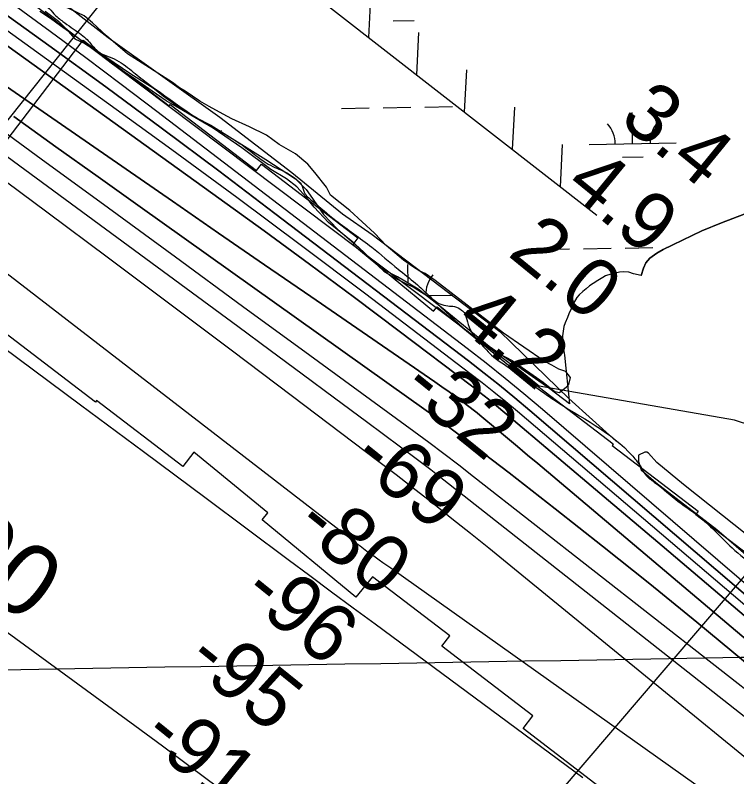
# Model space of a CAD drawing. Extents: x 3887375 to 3925618, y 296674 to 322633.
# Drawn here: x 3893263 to 3894095, y 314133 to 315011 of the extents above; entities that cross this region are included whole.
import ezdxf

# ---------------------------------------------------------------- set-up
doc = ezdxf.new("R2010")
doc.units = 0
for name, color, linetype in [('V-GRID-MAJR', 7, 'Continuous'), ('V-RIVR-EDGE', 7, 'Continuous'), ('V-RIVR-JETY', 7, 'Continuous'), ('V-RIVR-RANG', 7, 'Continuous'), ('V-RRAP-FSHR', 7, 'Continuous'), ('V-RRAP-RVMT', 7, 'Continuous'), ('V-TOPO-DPTH', 7, 'Continuous'), ('V-TOPO-MAJR', 7, 'Continuous'), ('V-TOPO-MINR', 7, 'Continuous'), ('V-TOPO-MINR-IDEN', 7, 'Continuous'), ('V-TOPO-SHOR', 7, 'Continuous'), ('V-TOPO-WATR', 7, 'Continuous'), ('V-WETL-SWMP', 7, 'Continuous')]:
    doc.layers.add(name, color=color, linetype=linetype)

msp = doc.modelspace()

# ---------------------------------------------------------------- linework, layer by layer
at = {"layer": 'V-GRID-MAJR'}
msp.add_spline([(3891444.7, 314225.88), (3896753.86, 314315.07), (3902063.01, 314405.04), (3907372.14, 314495.79), (3912681.27, 314587.3), (3917990.38, 314679.59), (3923299.47, 314772.65)], degree=3, dxfattribs=at)
at = {"layer": 'V-RIVR-EDGE'}
msp.add_spline([(3891928.45, 315977.82), (3891957.1, 315960.21), (3891975.01, 315952.59), (3891990.13, 315943.39), (3892009.63, 315930.59), (3892033.91, 315917.77), (3892077.69, 315895.35), (3892112.31, 315874.14), (3892145.74, 315852.54), (3892173.98, 315832.54), (3892316.06, 315752.48), (3892341.13, 315737.67), (3892375.37, 315721.25), (3892402.44, 315708.83), (3892426.71, 315696.01), (3892453.78, 315682.4), (3892471.29, 315671.99), (3892523.02, 315638.79), (3892560.03, 315617.57), (3892582.31, 315601.18), (3892604.59, 315586.77), (3892621.3, 315577.17), (3892636.02, 315565.57), (3892664.25, 315537.61), (3892674.17, 315522.84), (3892678.13, 315511.67), (3892682.1, 315505.28), (3892690.46, 315500.88), (3892696.83, 315498.47), (3892706.77, 315489.28), (3892723.47, 315474.49), (3892741.76, 315455.72), (3892761.64, 315438.13), (3892777.55, 315422.55), (3892805.39, 315399.37), (3892826.47, 315384.57), (3892845.56, 315369.38), (3892875, 315344.99), (3892902.83, 315321.41), (3892934.64, 315289.85), (3892954.52, 315270.67), (3892974.01, 315257.47), (3892987.54, 315247.07), (3892996.68, 315235.89), (3893002.63, 315225.52), (3893020.54, 315215.51), (3893037.65, 315206.7), (3893043.62, 315202.3), (3893054.76, 315193.5), (3893076.25, 315182.69), (3893088.99, 315175.48), (3893097.73, 315167.09), (3893110.86, 315156.7), (3893119.61, 315149.5), (3893128.77, 315145.5), (3893137.53, 315143.48), (3893147.48, 315138.28), (3893164.98, 315124.68), (3893182.88, 315109.1), (3893203.96, 315093.9), (3893217.49, 315085.9), (3893226.64, 315076.71), (3893239.37, 315067.91), (3893248.51, 315057.52), (3893271.97, 315035.94), (3893289.87, 315023.54), (3893300.23, 315019.93), (3893307.78, 315012.34), (3893318.12, 315003.55), (3893337.21, 314989.95), (3893344.77, 314983.95), (3893355.11, 314972.37), (3893362.66, 314966.37), (3893374.61, 314961.56), (3893394.9, 314948.76), (3893412.4, 314934.77), (3893439.06, 314915.57), (3893461.33, 314899.57), (3893504.71, 314873.56), (3893525, 314860.76), (3893540.52, 314849.16), (3893560.01, 314836.36), (3893578.33, 314827.95), (3893587.08, 314821.55), (3893592.64, 314815.96), (3893596.21, 314806.78), (3893605.35, 314796.8), (3893632.79, 314774.01), (3893674.16, 314743.22), (3893704.39, 314718.04), (3893724.67, 314701.65), (3893740.18, 314687.26), (3893752.51, 314678.07), (3893761.67, 314675.65), (3893769.64, 314674.84), (3893777.6, 314670.83), (3893781.18, 314666.84), (3893784.35, 314657.26), (3893789.1, 314645.69), (3893797.04, 314635.31), (3893812.15, 314618.94), (3893836.42, 314601.74), (3893870.23, 314576.95), (3893883.36, 314567.75), (3893974.86, 314502.16), (3893984.39, 314489.38), (3893990.75, 314479.8), (3894001.09, 314471.41), (3894027.34, 314450.22), (3894050.41, 314433.43), (3894069.1, 314416.64), (3894089.38, 314396.66), (3894117.62, 314375.07), (3894129.56, 314367.47), (3894149.44, 314351.08), (3894187.62, 314319.5), (3894217.45, 314293.92), (3894236.15, 314278.73), (3894249.67, 314267.94), (3894262.79, 314253.96), (3894279.09, 314238.38)], degree=3, dxfattribs=at)
at = {"layer": 'V-RIVR-JETY'}
for points in [[(3893297.79, 315015.6), (3893313.01, 315003.96), (3893321.96, 314995), (3893331.81, 314983.36), (3893343.45, 314977.99), (3893367.63, 314962.77), (3893396.28, 314943.07), (3893422.25, 314926.95), (3893433.89, 314918), (3893450.9, 314905.46), (3893471.5, 314892.93), (3893488.51, 314883.97), (3893552.08, 314844.57), (3893586.11, 314822.19), (3893598.64, 314809.65), (3893603.12, 314803.39), (3893618.34, 314781), (3893634.46, 314763.99), (3893658.64, 314743.39), (3893673.86, 314729.07), (3893688.18, 314715.64), (3893702.51, 314706.68), (3893713.26, 314701.31), (3893723.11, 314696.83), (3893742.8, 314684.3), (3893758.92, 314669.07), (3893779.52, 314650.27), (3893798.32, 314635.05), (3893818.91, 314621.62), (3893835.93, 314612.66), (3893871.74, 314587.59), (3893885.18, 314576.85), (3893890.55, 314575.95), (3893898.61, 314582.22), (3893901.29, 314584.91), (3893903.08, 314592.96), (3893897.71, 314600.13), (3893889.65, 314602.81), (3893881.59, 314607.29), (3893872.64, 314611.77), (3893826.08, 314644), (3893747.28, 314704.89), (3893735.64, 314712.95), (3893729.37, 314715.64), (3893722.21, 314720.11), (3893710.57, 314728.17), (3893690.87, 314745.18), (3893677.44, 314759.51), (3893648.79, 314785.48), (3893626.4, 314803.39), (3893621.92, 314812.34), (3893608.49, 314829.35), (3893600.43, 314839.2), (3893586.11, 314850.84), (3893567.3, 314861.59), (3893552.98, 314872.33), (3893533.28, 314882.18), (3893512.68, 314891.14), (3893502.83, 314896.51), (3893486.72, 314905.46), (3893475.97, 314911.73), (3893458.96, 314923.37), (3893452.69, 314926.95), (3893444.63, 314933.22), (3893392.7, 314966.35), (3893368.52, 314986.95), (3893352.41, 315002.17), (3893342.56, 315010.23), (3893312.11, 315024.55)], [(3894136.46, 314387.99), (3894033.49, 314469.73), (3894002.71, 314495.2), (3893993.15, 314505.82), (3893991.03, 314506.88), (3893988.91, 314506.88), (3893981.48, 314503.69), (3893981.48, 314496.26), (3893984.66, 314486.71), (3894001.64, 314471.85), (3894071.7, 314417.71), (3894116.29, 314379.5)]]:
    msp.add_lwpolyline(points, dxfattribs=at)
at = {"layer": 'V-RIVR-RANG'}
for p, q in [((3893474.49, 315166.64), (3892839.24, 314368.61)), ((3894256.41, 314543.27), (3893593.48, 313768.08))]:
    msp.add_line(p, q, dxfattribs=at)
at = {"layer": 'V-RRAP-FSHR'}
for p, q in [((3893670.74, 314985.25), (3893673.25, 315034.01)), ((3893725.93, 314942.2), (3893728.45, 314990.96)), ((3893781.13, 314899.15), (3893783.65, 314947.91)), ((3893836.33, 314856.1), (3893838.84, 314904.86)), ((3893891.52, 314813.05), (3893894.04, 314861.81))]:
    msp.add_line(p, q, dxfattribs=at)
for points in [[(3893118.1, 315414.89), (3893508.75, 315111.58), (3893933.55, 314780.27)], [(3892945.61, 315305.74), (3893066.47, 315208.61), (3893128.78, 315157.3), (3893179.77, 315133.47), (3893370.49, 314985.02), (3893498.9, 314893.39), (3893581.99, 314829.25), (3893640.53, 314781.6), (3893674.52, 314757.77), (3893821.81, 314645.98), (3893901.13, 314569.01), (3893955.89, 314519.53)], [(3893387.89, 315205.42), (3893508.75, 315111.58), (3893933.55, 314780.27)]]:
    msp.add_lwpolyline(points, dxfattribs=at)
at = {"layer": 'V-RRAP-RVMT'}
for p, q in [((3893238.49, 314847.17), (3893341.39, 314981.83)), ((3893341.39, 314981.83), (3893440.65, 314906.15)), ((3893440.65, 314906.15), (3893441.91, 314907.76)), ((3893441.91, 314907.76), (3893541.36, 314831.84)), ((3893541.36, 314831.84), (3893546.88, 314839.04)), ((3893546.88, 314839.04), (3893658.15, 314754.03)), ((3893658.15, 314754.03), (3893652.16, 314746.26)), ((3893652.16, 314746.26), (3893745.41, 314669.51)), ((3893745.41, 314669.51), (3893749.61, 314674.55)), ((3893749.61, 314674.55), (3893840.1, 314600.22)), ((3893355.69, 314564.59), (3893244.5, 314649.6)), ((3893840.1, 314600.22), (3893841.1, 314601.49)), ((3893841.1, 314601.49), (3893952.31, 314516.38)), ((3893357.03, 314566.38), (3893355.69, 314564.59)), ((3893456.4, 314490.41), (3893357.03, 314566.38)), ((3893952.31, 314516.38), (3893951.05, 314514.76)), ((3893951.05, 314514.76), (3894050.29, 314438.8)), ((3893468.93, 314506.94), (3893456.4, 314490.41)), ((3893554.25, 314436.9), (3893468.93, 314506.94)), ((3893547.7, 314428.93), (3893554.25, 314436.9)), ((3894050.29, 314438.8), (3894047.54, 314435.22)), ((3894047.54, 314435.22), (3894152.28, 314354.98)), ((3893655.81, 314339.96), (3893547.7, 314428.93)), ((3893674.99, 314363.29), (3893655.81, 314339.96)), ((3893764.18, 314295.24), (3893674.99, 314363.29)), ((3893754.98, 314283.22), (3893764.18, 314295.24)), ((3893859.8, 314202.83), (3893754.98, 314283.22)), ((3893848.65, 314188.24), (3893859.8, 314202.83)), ((3893947.76, 314112.32), (3893848.65, 314188.24))]:
    msp.add_line(p, q, dxfattribs=at)
at = {"layer": 'V-TOPO-DPTH'}
for points in [[(3894391.72, 314096.09), (3894339.08, 314141.49), (3894307.72, 314168.51), (3894276.34, 314195.5), (3894244.93, 314222.45), (3894213.5, 314249.37), (3893856.33, 314555.02), (3893838.93, 314569.66), (3893821.36, 314584.1), (3893803.55, 314598.24), (3893785.58, 314612.18), (3893562.45, 314782.26), (3893497.73, 314831.21), (3893432.77, 314879.85), (3893367.46, 314928.01), (3893301.91, 314975.85), (3893201.46, 315048.6)], [(3893201.46, 315048.6), (3893301.91, 314975.85), (3893367.46, 314928.01), (3893432.77, 314879.85), (3893497.73, 314831.21), (3893562.45, 314782.26), (3893785.58, 314612.18), (3893803.55, 314598.24), (3893821.36, 314584.1), (3893838.93, 314569.66), (3893856.33, 314555.02), (3894213.5, 314249.37), (3894244.93, 314222.45), (3894276.34, 314195.5), (3894307.72, 314168.51), (3894339.08, 314141.49), (3894391.72, 314096.09)], [(3895356.45, 313608.97), (3895202.61, 313769.6), (3895185.66, 313787.43), (3895168.79, 313805.34), (3895152.06, 313823.38), (3895135.42, 313841.49), (3895020.97, 313966.99), (3894983.49, 314007.86), (3894945.86, 314048.59), (3894907.99, 314089.11), (3894869.98, 314129.49), (3894830.99, 314168.81), (3894790.87, 314206.89), (3894621.93, 314337.77), (3894383.23, 314448.72), (3894091.96, 314544.03), (3893867.05, 314583.12), (3893838.43, 314605.12), (3893809.72, 314626.99), (3893780.94, 314648.78), (3893286.1, 315021.75), (3893269.81, 315033.97), (3893253.49, 315046.13)], [(3893207.69, 315008.59), (3893497.98, 314799.91), (3893550.27, 314762.02), (3893602.36, 314723.87), (3893654.15, 314685.31), (3893705.76, 314646.5), (3893788.97, 314583.4), (3893798.76, 314575.85), (3893808.46, 314568.21), (3893818.03, 314560.4), (3893827.53, 314552.5), (3893942.02, 314455.57), (3894008.66, 314399.08), (3894075.24, 314342.53), (3894141.75, 314285.88), (3894208.2, 314229.17), (3894366.18, 314094.17)], [(3893207.69, 315008.59), (3893497.98, 314799.91), (3893550.27, 314762.02), (3893602.36, 314723.87), (3893654.15, 314685.31), (3893705.76, 314646.5), (3893788.97, 314583.4), (3893798.76, 314575.85), (3893808.46, 314568.21), (3893818.03, 314560.4), (3893827.53, 314552.5), (3893942.02, 314455.57), (3894008.66, 314399.08), (3894075.24, 314342.53), (3894141.75, 314285.88), (3894208.2, 314229.17), (3894366.18, 314094.17)], [(3894340.52, 314092.09), (3893865.37, 314493.75), (3893853.76, 314503.55), (3893842.14, 314513.33), (3893830.51, 314523.09), (3893818.87, 314532.85), (3893798.58, 314549.81), (3893795.54, 314552.29), (3893793.99, 314553.5), (3893792.43, 314554.7), (3893779.45, 314564.51), (3893771.35, 314570.55), (3893763.2, 314576.51), (3893754.96, 314582.36), (3893746.68, 314588.14), (3893656.97, 314649.81), (3893603.8, 314686.39), (3893550.65, 314722.99), (3893497.52, 314759.63), (3893444.41, 314796.29), (3893204.51, 314962.02)], [(3893204.51, 314962.02), (3893444.41, 314796.29), (3893497.52, 314759.63), (3893550.65, 314722.99), (3893603.8, 314686.39), (3893656.97, 314649.81), (3893746.68, 314588.14), (3893754.96, 314582.36), (3893763.2, 314576.51), (3893771.35, 314570.55), (3893779.45, 314564.51), (3893792.43, 314554.7), (3893793.99, 314553.5), (3893795.54, 314552.29), (3893798.58, 314549.81), (3893818.87, 314532.85), (3893830.51, 314523.09), (3893842.14, 314513.33), (3893853.76, 314503.55), (3893865.37, 314493.75), (3894340.52, 314092.09)], [(3894314.2, 314089.78), (3894102.47, 314266.53), (3894048.71, 314310.96), (3893994.67, 314355.04), (3893940.2, 314398.58), (3893885.44, 314441.76), (3893832.31, 314483.25), (3893803.76, 314505.23), (3893775.02, 314526.96), (3893745.99, 314548.31), (3893716.77, 314569.4), (3893407.27, 314789.68), (3893358.67, 314824.38), (3893310.13, 314859.17), (3893261.7, 314894.1)], [(3893261.7, 314894.1), (3893310.13, 314859.17), (3893358.67, 314824.38), (3893407.27, 314789.68), (3893716.77, 314569.4), (3893745.99, 314548.31), (3893775.02, 314526.96), (3893803.76, 314505.23), (3893832.31, 314483.25), (3893885.44, 314441.76), (3893940.2, 314398.58), (3893994.67, 314355.04), (3894048.71, 314310.96), (3894102.47, 314266.53), (3894314.2, 314089.78)]]:
    msp.add_lwpolyline(points, dxfattribs=at)
at = {"layer": 'V-TOPO-MAJR'}
msp.add_lwpolyline([(3894245.15, 314121.68), (3894208.72, 314151.19), (3894172.07, 314180.41), (3894135.27, 314209.45), (3893791.46, 314478.57), (3893774.35, 314491.83), (3893757.15, 314504.98), (3893739.83, 314517.96), (3893722.42, 314530.84), (3893602.65, 314618.5), (3893525.28, 314675.11), (3893447.91, 314731.72), (3893370.53, 314788.3), (3893293.14, 314844.88), (3893143.53, 314954.24)], dxfattribs=at)
at = {"layer": 'V-TOPO-MINR'}
for points in [[(3894391.72, 314096.09), (3894339.08, 314141.49), (3894307.72, 314168.51), (3894276.34, 314195.5), (3894244.93, 314222.45), (3894213.5, 314249.37), (3893856.33, 314555.02), (3893838.93, 314569.66), (3893821.36, 314584.1), (3893803.55, 314598.24), (3893785.58, 314612.18), (3893562.45, 314782.26), (3893497.73, 314831.21), (3893432.77, 314879.85), (3893367.46, 314928.01), (3893301.91, 314975.85), (3893201.46, 315048.6)], [(3894378.97, 314095.15), (3894287.47, 314173.72), (3894233.24, 314220.21), (3894178.98, 314266.67), (3894124.66, 314313.05), (3894070.3, 314359.38), (3893841.94, 314553.78), (3893828.49, 314565.04), (3893814.91, 314576.15), (3893801.15, 314587.04), (3893787.27, 314597.78), (3893667.25, 314689.02), (3893593.06, 314744.98), (3893518.59, 314800.57), (3893443.71, 314855.6), (3893368.55, 314910.26), (3893204.56, 315028.57)], [(3894368.41, 314128.19), (3894358.58, 314136.66), (3894348.74, 314145.13), (3893870.69, 314556.23), (3893849.35, 314574.26), (3893827.81, 314592.04), (3893805.96, 314609.45), (3893783.91, 314626.61), (3893426.29, 314899.94), (3893385.48, 314930.9), (3893344.52, 314961.66), (3893303.34, 314992.13), (3893262.01, 315022.41)], [(3894366.18, 314094.17), (3894208.2, 314229.17), (3894141.75, 314285.88), (3894075.24, 314342.53), (3894008.66, 314399.08), (3893942.02, 314455.57), (3893827.53, 314552.5), (3893818.03, 314560.4), (3893808.46, 314568.21), (3893798.76, 314575.85), (3893788.97, 314583.4), (3893705.76, 314646.5), (3893654.15, 314685.31), (3893602.36, 314723.87), (3893550.27, 314762.02), (3893497.98, 314799.91), (3893207.69, 315008.59)], [(3894340.52, 314092.09), (3893865.37, 314493.75), (3893853.76, 314503.55), (3893842.14, 314513.33), (3893830.51, 314523.09), (3893818.87, 314532.85), (3893798.58, 314549.81), (3893795.54, 314552.29), (3893793.99, 314553.5), (3893792.43, 314554.7), (3893779.45, 314564.51), (3893771.35, 314570.55), (3893763.2, 314576.51), (3893754.96, 314582.36), (3893746.68, 314588.14), (3893656.97, 314649.81), (3893603.8, 314686.39), (3893550.65, 314722.99), (3893497.52, 314759.63), (3893444.41, 314796.29), (3893204.51, 314962.02)], [(3894276.4, 314014.39), (3893851.13, 314361.81), (3893830.04, 314378.99), (3893808.92, 314396.14), (3893787.75, 314413.22), (3893766.56, 314430.28), (3893745.27, 314447.21), (3893723.89, 314464.02), (3893702.37, 314480.64), (3893680.75, 314497.15), (3893582.91, 314571.19), (3893512.23, 314624.54), (3893441.46, 314677.77), (3893370.57, 314730.82), (3893299.58, 314783.76), (3893085.06, 314943.3)], [(3894209.43, 314117.45), (3894166.43, 314151.96), (3894123.28, 314186.29), (3894080.04, 314220.49), (3893757.29, 314474.67), (3893749.71, 314480.59), (3893742.11, 314486.47), (3893734.46, 314492.28), (3893726.77, 314498.06), (3893668.13, 314541.79), (3893631.07, 314569.37), (3893593.98, 314596.9), (3893556.83, 314624.36), (3893519.66, 314651.77), (3893147.67, 314925.47)], [(3894314.2, 314089.78), (3894102.47, 314266.53), (3894048.71, 314310.96), (3893994.67, 314355.04), (3893940.2, 314398.58), (3893885.44, 314441.76), (3893832.31, 314483.25), (3893803.76, 314505.23), (3893775.02, 314526.96), (3893745.99, 314548.31), (3893716.77, 314569.4), (3893407.27, 314789.68), (3893358.67, 314824.38), (3893310.13, 314859.17), (3893261.7, 314894.1)], [(3894200.22, 314015.1), (3893695.92, 314373.06), (3893691.45, 314376.23), (3893686.99, 314379.4), (3893682.51, 314382.56), (3893678.04, 314385.72), (3893670.25, 314391.22), (3893669.68, 314391.63), (3893668.53, 314392.46), (3893666.52, 314393.94), (3893662.68, 314396.9), (3893660.61, 314398.49), (3893658.54, 314400.08), (3893656.48, 314401.67), (3893654.41, 314403.26), (3893053.24, 314867)], [(3893917.41, 314131.46), (3893677.86, 314308.63), (3893652.84, 314327.16), (3893627.84, 314345.71), (3893602.85, 314364.29), (3893577.89, 314382.89), (3893483.25, 314453.5), (3893410.95, 314507.39), (3893338.61, 314561.23), (3893266.22, 314615), (3893193.8, 314668.72)], [(3892953.66, 314518.69), (3893400.91, 314191.75), (3893432.83, 314168.28), (3893464.67, 314144.7), (3893496.39, 314120.94), (3893528.02, 314097.07), (3893537.4, 314089.96), (3893573.57, 314062.33), (3893609.62, 314034.55), (3893645.49, 314006.54), (3893681.25, 313978.39), (3894026.21, 313704.98), (3894044.41, 313690.64), (3894062.67, 313676.37), (3894081.01, 313662.2), (3894099.4, 313648.1), (3894175.93, 313589.8), (3894233.1, 313547.27), (3894290.88, 313505.62), (3894349.6, 313465.3), (3894408.95, 313425.87), (3894570.06, 313321.43)]]:
    msp.add_lwpolyline(points, dxfattribs=at)
at = {"layer": 'V-TOPO-SHOR'}
for points in [[(3893984.43, 314710.85), (3893987.19, 314719.04), (3893989.92, 314725.26), (3893994.62, 314730.46), (3894002.62, 314736.6), (3894009.93, 314740.45), (3894032.18, 314751.31), (3894054.43, 314762.17), (3894076.98, 314771.38), (3894103.17, 314781.19)], [(3893984.43, 314710.85), (3893975.58, 314712.76), (3893970.28, 314714.62), (3893964.06, 314714.72), (3893959.61, 314714.34), (3893953.38, 314713.1), (3893949.81, 314712.27)], [(3893949.81, 314712.27), (3893943.56, 314710.15), (3893940.42, 314708.42), (3893934.6, 314704.96), (3893929.22, 314701.49), (3893925.18, 314698.88), (3893921.13, 314695.39), (3893917.53, 314692.34), (3893913.03, 314688.41), (3893910.31, 314685.35), (3893906.2, 314677.86), (3893903.89, 314672.12), (3893901.14, 314666.39), (3893899.75, 314662.41), (3893896.98, 314656.24), (3893895.58, 314651.82), (3893894.09, 314641.19), (3893894.03, 314637.63), (3893894.37, 314630.52), (3893896.41, 314618.94), (3893901.96, 314562.84)]]:
    msp.add_lwpolyline(points, dxfattribs=at)
at = {"layer": 'V-TOPO-WATR'}
msp.add_lwpolyline([(3895356.45, 313608.97), (3895202.61, 313769.6), (3895185.66, 313787.43), (3895168.79, 313805.34), (3895152.06, 313823.38), (3895135.42, 313841.49), (3895020.97, 313966.99), (3894983.49, 314007.86), (3894945.86, 314048.59), (3894907.99, 314089.11), (3894869.98, 314129.49), (3894830.99, 314168.81), (3894790.87, 314206.89), (3894621.93, 314337.77), (3894383.23, 314448.72), (3894091.96, 314544.03), (3893867.05, 314583.12), (3893838.43, 314605.12), (3893809.72, 314626.99), (3893780.94, 314648.78), (3893286.1, 315021.75), (3893269.81, 315033.97), (3893253.49, 315046.13)], dxfattribs=at)
at = {"layer": 'V-WETL-SWMP'}
for p, q in [((3893303.93, 315006.82), (3893291.4, 315015.01)), ((3893315.35, 314998.43), (3893303.93, 315006.82)), ((3893698.87, 315004.3), (3893722.87, 315004.72)), ((3893331.17, 314987.3), (3893315.35, 314998.43)), ((3893343.46, 314978.45), (3893331.17, 314987.3)), ((3893359.05, 314966.44), (3893343.46, 314978.45)), ((3893376.83, 314953.06), (3893359.05, 314966.44)), ((3893389.8, 314944.65), (3893376.83, 314953.06)), ((3893401.89, 314936.69), (3893389.8, 314944.65)), ((3893421.22, 314923.07), (3893401.89, 314936.69)), ((3893437.04, 314912.17), (3893421.22, 314923.07)), ((3893455.31, 314901.67), (3893437.04, 314912.17)), ((3893465.65, 314895.51), (3893455.31, 314901.67)), ((3893639.19, 314903.26), (3893671.19, 314903.81)), ((3893687.18, 314904.09), (3893719.18, 314904.64)), ((3893735.18, 314904.91), (3893767.17, 314905.46)), ((3893974.78, 314862.59), (3893974.16, 314898.58)), ((3893474.89, 314890.04), (3893465.65, 314895.51)), ((3893491.18, 314880.69), (3893474.89, 314890.04)), ((3893524.35, 314857.75), (3893491.18, 314880.69)), ((3893924.79, 314861.73), (3894024.78, 314863.45)), ((3893557.95, 314833.02), (3893524.35, 314857.75)), ((3893963.05, 314846.95), (3893987.05, 314847.37)), ((3893575.77, 314822.31), (3893557.95, 314833.02)), ((3893587.61, 314813.02), (3893575.77, 314822.31)), ((3893598.97, 314800.64), (3893587.61, 314813.02)), ((3893607.9, 314789.62), (3893598.97, 314800.64)), ((3893624.28, 314771.6), (3893607.9, 314789.62)), ((3894103.17, 314781.19), (3894076.98, 314771.38)), ((3893654.11, 314747.6), (3893624.28, 314771.6)), ((3894076.98, 314771.38), (3894054.43, 314762.17)), ((3894054.43, 314762.17), (3894032.18, 314751.31)), ((3894032.18, 314751.31), (3894009.93, 314740.45)), ((3893682.56, 314720.74), (3893654.11, 314747.6)), ((3893870.02, 314740.7), (3893902.01, 314741.25)), ((3893918.01, 314741.52), (3893950, 314742.07)), ((3893966, 314742.35), (3893998, 314742.9)), ((3894009.93, 314740.45), (3894002.62, 314736.6)), ((3894013.99, 314743.17), (3894015.58, 314743.2)), ((3894002.62, 314736.6), (3893994.62, 314730.47)), ((3893716.07, 314701.77), (3893715.7, 314723.31)), ((3893989.93, 314725.26), (3893987.19, 314719.05)), ((3893994.62, 314730.47), (3893989.93, 314725.26)), ((3893690.7, 314715.95), (3893682.56, 314720.74)), ((3893697.53, 314712.07), (3893690.7, 314715.95)), ((3893959.61, 314714.34), (3893953.38, 314713.1)), ((3893964.06, 314714.72), (3893959.61, 314714.34)), ((3893970.28, 314714.62), (3893964.06, 314714.72)), ((3893975.58, 314712.76), (3893970.28, 314714.62)), ((3893987.19, 314719.05), (3893984.43, 314710.85)), ((3893703.92, 314709.08), (3893697.53, 314712.07)), ((3893712.28, 314704.07), (3893703.92, 314709.08)), ((3893934.6, 314704.96), (3893929.22, 314701.49)), ((3893940.43, 314708.42), (3893934.6, 314704.96)), ((3893943.56, 314710.15), (3893940.43, 314708.42)), ((3893949.81, 314712.27), (3893943.56, 314710.15)), ((3893953.38, 314713.1), (3893949.81, 314712.27)), ((3893984.43, 314710.85), (3893975.58, 314712.76)), ((3893727.68, 314694.73), (3893712.28, 314704.07)), ((3893925.18, 314698.88), (3893921.13, 314695.39)), ((3893929.22, 314701.49), (3893925.18, 314698.88)), ((3893754.45, 314673.88), (3893727.68, 314694.73)), ((3893736.75, 314687.66), (3893766.31, 314688.17)), ((3893913.03, 314688.41), (3893910.31, 314685.35)), ((3893917.53, 314692.34), (3893913.03, 314688.41)), ((3893921.13, 314695.39), (3893917.53, 314692.34)), ((3893910.31, 314685.35), (3893906.2, 314677.86)), ((3893809.27, 314628.67), (3893754.45, 314673.88)), ((3893903.89, 314672.12), (3893901.14, 314666.39)), ((3893906.2, 314677.86), (3893903.89, 314672.12)), ((3893899.75, 314662.42), (3893896.99, 314656.24)), ((3893901.14, 314666.39), (3893899.75, 314662.42)), ((3893896.99, 314656.24), (3893895.58, 314651.82)), ((3893895.58, 314651.82), (3893894.09, 314641.19)), ((3893894.09, 314641.19), (3893894.03, 314637.63)), ((3893894.03, 314637.63), (3893894.37, 314630.52)), ((3893879.13, 314580.07), (3893809.27, 314628.67)), ((3893894.37, 314630.52), (3893896.41, 314618.94)), ((3893896.41, 314618.94), (3893901.96, 314562.84)), ((3893901.96, 314562.84), (3893879.13, 314580.07))]:
    msp.add_line(p, q, dxfattribs=at)
for centre, start, end in [((3893919.54, 314862.11), 0.21154, 41.7552), ((3894030.01, 314864.01), 140.21154, 181.75519), ((3893528.18, 314855.4), 140.21154, 145.73144), ((3893771.54, 314688.74), 140.21154, 181.17856)]:
    msp.add_arc(centre, 35.25, start, end, dxfattribs=at)

# ---------------------------------------------------------------- texts
at = {"layer": 'V-RIVR-RANG'}
for s, rotation, p in [('3.4', 320.78833, (3893957.8, 314887.9)), ('4.9', 320.78833, (3893894.57, 314810.43)), ('2.0', 320.78833, (3893829.5, 314734.46)), ('4.2', 320.78833, (3893768.72, 314654.99)), ('-32', 321.07206, (3893706.17, 314576.42)), ('-69', 321.07206, (3893648.28, 314494.64)), ('-80', 321.07206, (3893583.61, 314418.33)), ('-96', 321.07206, (3893522.02, 314339.53)), ('-95', 321.07206, (3893457.76, 314262.88)), ('-91', 321.07206, (3893406.84, 314175.47))]:
    msp.add_text(s, height=67, rotation=rotation, dxfattribs=at).set_placement(p)
at = {"layer": 'V-TOPO-MINR-IDEN'}
msp.add_text('-90', height=83, rotation=323.83275, dxfattribs=at).set_placement((3893147.01, 314403.05))

doc.saveas('drawing.dxf')
